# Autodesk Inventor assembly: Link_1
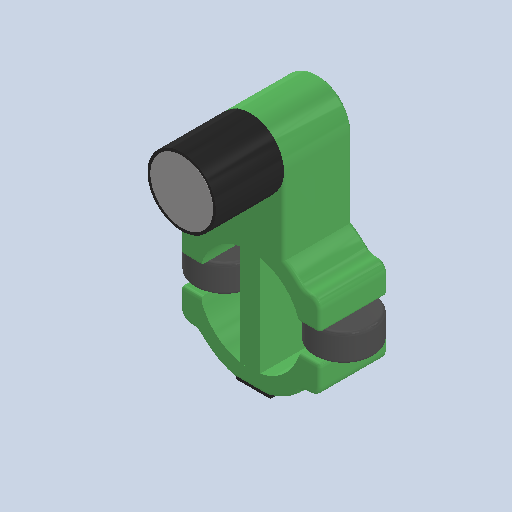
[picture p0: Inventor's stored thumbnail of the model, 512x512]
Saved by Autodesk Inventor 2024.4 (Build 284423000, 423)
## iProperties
Created: 2025-07
Part Number: Link_1
Document SubType Name: Assembly
Designer: AdminForWorker
Title: Link_1 v2
Author: AdminForWorker
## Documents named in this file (6)
- c:\worker\convert-fusion-r03-cosv3\tmp\job-1\6\temp\files\cc6a613c-d371-4aaf-a205-cf1d6fdf3267\Link_1 v2.iam
- c:\worker\convert-fusion-r03-cosv3\tmp\job-1\6\temp\files\cc6a613c-d371-4aaf-a205-cf1d6fdf3267\Plate v1.ipt
- c:\worker\convert-fusion-r03-cosv3\tmp\job-1\6\temp\files\cc6a613c-d371-4aaf-a205-cf1d6fdf3267\Pulley v1.ipt
- c:\worker\convert-fusion-r03-cosv3\tmp\job-1\6\temp\files\cc6a613c-d371-4aaf-a205-cf1d6fdf3267\Seal v1.ipt
- c:\worker\convert-fusion-r03-cosv3\tmp\job-1\6\temp\files\cc6a613c-d371-4aaf-a205-cf1d6fdf3267\Bolt v1.ipt
- c:\worker\convert-fusion-r03-cosv3\tmp\job-1\6\temp\files\cc6a613c-d371-4aaf-a205-cf1d6fdf3267\Part12.ipt
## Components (7 placed, 5 different names)
1. Plate v1:1
2. Pulley v1:1
3. Seal v1:1
4. Bolt v1:1
5. Bolt v1:2
6. Pulley v1:2
7. Part12
